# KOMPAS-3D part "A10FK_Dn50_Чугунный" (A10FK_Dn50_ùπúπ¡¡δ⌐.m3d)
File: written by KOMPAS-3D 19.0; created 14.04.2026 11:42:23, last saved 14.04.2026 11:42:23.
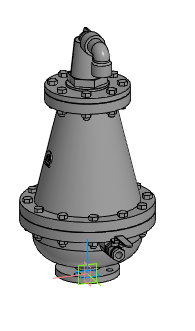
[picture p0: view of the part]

Document properties: Автор: Энергия; Полное имя файла: Z:\3.Личные\kachalov\3d для проектировщиков\x.x Тип A10FK Двухступенчатый воздухоотводчик\stp_Тип A10FK Двухступенчатый воздухоотводчик\A10FK_Dn50_Чугунный.m3d

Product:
- Part/product: A10FK_Dn50_Чугунный

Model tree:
1. Операция без истории:1  (labels: A10FK_Dn50_Чугунный)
